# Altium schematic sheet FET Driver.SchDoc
size 431 x 279 mm; Date: Not shown in title block; ApprovedBy: Not shown in title block; CheckedBy: Not shown in title block; Author: Not shown in title block; CompanyName: Not shown in title block; Engineer: Not shown in title block; Organization: Not shown in title block; Address1: Not shown in title block; Address2: Not shown in title block; Address3: Not shown in title block; Address4: Not shown in title block; DocumentNumber: 1; Revision: Use project parameter SCH_Rev; SheetNumber: 2; SheetTotal: 3; PageSetup: Record=PageOptions¦CenterHorizontal=True¦CenterVertical=True¦PrintScale=1.00¦XCorrection=1.00¦YCorrection=1.00¦PrintKind=0¦BorderSize=5000000¦LeftOffset=0¦BottomOffset=0¦Orientation=2¦PaperLength=1000¦PaperWidth=1000¦Scale=100¦PaperSource=15¦PrintQuality=600¦MediaType=1¦DitherType=10¦PaperKind=Letter¦PrintScaleMode=1
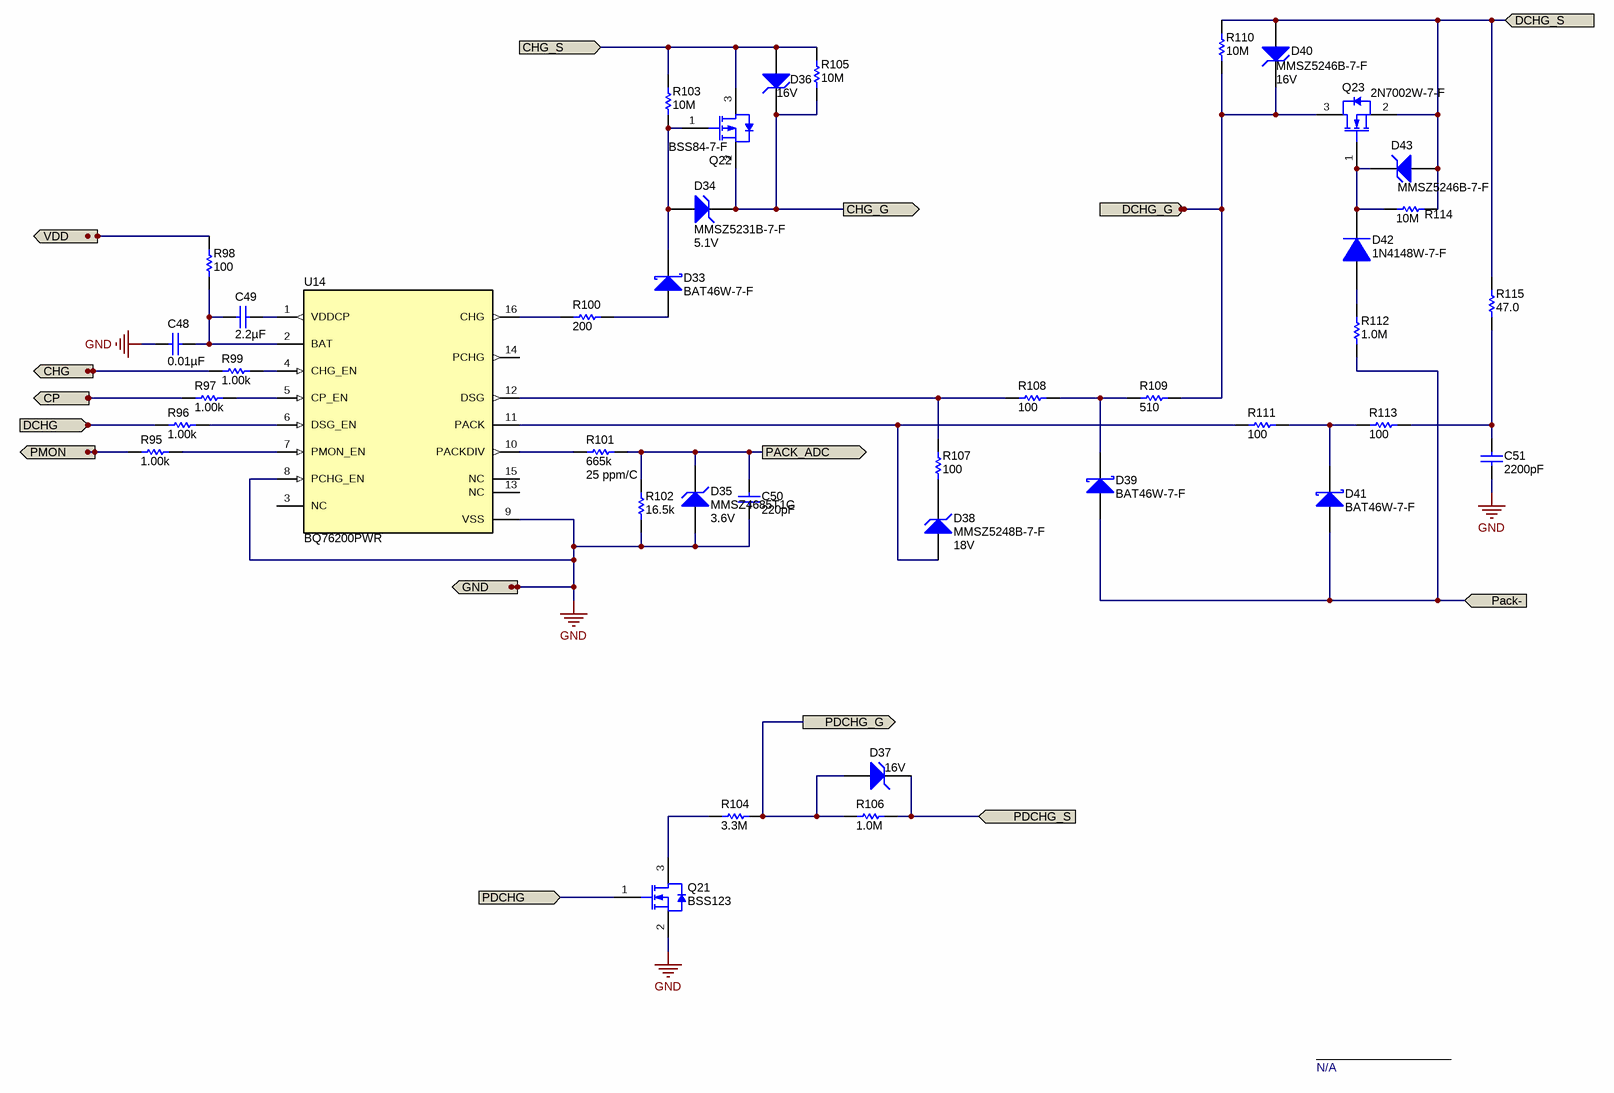
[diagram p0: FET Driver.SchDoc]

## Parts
C48  ValueDisplayed: 0.01µF  [0603]  (hidden comment: GRM188R72A103KA01D)
C49  ValueDisplayed: 2.2µF  [0805_HV]  (hidden comment: C2012X7R1V225K085AC)
C50  ValueDisplayed: 220pF  [0603]  (hidden comment: GRM188R71H221KA01D)
C51  ValueDisplayed: 2200pF  [0603]  (hidden comment: 06031C222JAT2A)
D33  BAT46W-7-F  [SOD-123]
D34  MMSZ5231B-7-F  value 5.1V  [SOD-123]
D35  MMSZ4685T1G  value 3.6V  [SOD-123]
D36  value 16V  [SOD-123]  (hidden comment: MMSZ5246B-7-F)
D37  value 16V  [SOD-123]  (hidden comment: MMSZ5246B-7-F)
D38  MMSZ5248B-7-F  value 18V  [SOD-123]
D39  BAT46W-7-F  [SOD-123]
D40  MMSZ5246B-7-F  value 16V  [SOD-123]
D41  BAT46W-7-F  [SOD-123]
D42  1N4148W-7-F  [SOD-123]
D43  MMSZ5246B-7-F  [SOD-123]
Q21  BSS123  [SOT-23]
Q22  BSS84-7-F  [SOT-23]
Q23  2N7002W-7-F  [SOT-323]
R95  ValueDisplayed: 1.00k  [0603]  (hidden comment: CRCW06031K00FKEA)
R96  ValueDisplayed: 1.00k  [0603]  (hidden comment: CRCW06031K00FKEA)
R97  ValueDisplayed: 1.00k  [0603]  (hidden comment: CRCW06031K00FKEA)
R98  ValueDisplayed: 100  [0603]  (hidden comment: CRCW0603100RFKEA)
R99  ValueDisplayed: 1.00k  [0603]  (hidden comment: CRCW06031K00FKEA)
R100  ValueDisplayed: 200  [0603]  (hidden comment: CRCW0603200RFKEA)
R101  ValueDisplayed: 665k  TempCo: 25 ppm/C  [0603]  (hidden comment: RT0603BRD07665KL)
R102  ValueDisplayed: 16.5k  [0603]  (hidden comment: RT0603BRD0716K5L)
R103  ValueDisplayed: 10M  [0603]  (hidden comment: CRCW060310M0JNEA)
R104  ValueDisplayed: 3.3M  [0603]  (hidden comment: CRCW06033M30JNEA)
R105  ValueDisplayed: 10M  [0603]  (hidden comment: CRCW060310M0JNEA)
R106  ValueDisplayed: 1.0M  [0603]  (hidden comment: CRCW06031M00JNEA)
R107  ValueDisplayed: 100  [0603]  (hidden comment: CRCW0603100RFKEA)
R108  ValueDisplayed: 100  [0603S]  (hidden comment: CRCW0603100RFKEA)
R109  ValueDisplayed: 510  [0603]  (hidden comment: CRCW0603510RJNEA)
R110  ValueDisplayed: 10M  [0603]  (hidden comment: CRCW060310M0JNEA)
R111  ValueDisplayed: 100  [0603]  (hidden comment: CRCW0603100RFKEA)
R112  ValueDisplayed: 1.0M  [0603]  (hidden comment: CRCW06031M00JNEA)
R113  ValueDisplayed: 100  [0603]  (hidden comment: CRCW0603100RFKEA)
R114  ValueDisplayed: 10M  [0603]  (hidden comment: CRCW060310M0JNEA)
R115  ValueDisplayed: 47.0  [0603]  (hidden comment: RC0603FR-0747RL)
U14  BQ76200PWR  [PW0016A_L]

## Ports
CHG (in), CHG_G (out), CHG_S (in), CP (in), DCHG (in), DCHG_G (out), DCHG_S (in), GND (in), Pack- (in), PACK_ADC (out), PDCHG (in), PDCHG_G (out), PDCHG_S (in), PMON (in), VDD (in)

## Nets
GND: C48.2 C50.2 C51.2 D35.2(A) Q21.2(S) R102.1 U14.8(PCHG_EN) U14.9(VSS) ; port GND
CHG: R99.1 ; port CHG
CHG_G: D34.1(K) D36.1(K) Q22.2(S) R105.1 ; port CHG_G
CHG_S: D36.2(A) Q22.3(D) R103.2 R105.2 ; port CHG_S
CP: R97.1 ; port CP
DCHG: R96.1 ; port DCHG
DCHG_G: D40.1(K) Q23.3(D) R109.2 R110.1 ; port DCHG_G
DCHG_S: D40.2(A) D43.2(A) Q23.2(S) R110.2 R114.1 R115.2 ; port DCHG_S
Pack-: D39.2(A) D41.2(A) R112.1 ; port Pack-
PACK_ADC: C50.1 D35.1(K) R101.2 R102.2 ; port PACK_ADC
PDCHG: Q21.1(G) ; port PDCHG
PDCHG_G: D37.2(A) R104.2 R106.1 ; port PDCHG_G
PDCHG_S: D37.1(K) R106.2 ; port PDCHG_S
PMON: R95.1 ; port PMON
VDD: R98.2 ; port VDD
NetC48_1: C48.1 C49.2 R98.1 U14.2(BAT)
NetC49_1: C49.1 U14.1(VDDCP)
NetC51_1: C51.1 R113.2 R115.1
NetD33_1: D33.1(K) D34.2(A) Q22.1(G) R103.1
NetD33_2: D33.2(A) R100.2
NetD38_1: D38.1(K) R107.1
NetD38_2: D38.2(A) R111.1 U14.11(PACK)
NetD39_1: D39.1(K) R108.2 R109.1
NetD41_1: D41.1(K) R111.2 R113.1
NetD42_1: D42.1(K) D43.1(K) Q23.1(G) R114.2
NetD42_2: D42.2(A) R112.2
NetQ21_3: Q21.3(D) R104.1
NetR95_2: R95.2 U14.7(PMON_EN)
NetR96_2: R96.2 U14.6(DSG_EN)
NetR97_2: R97.2 U14.5(CP_EN)
NetR99_2: R99.2 U14.4(CHG_EN)
NetR100_1: R100.1 U14.16(CHG)
NetR101_1: R101.1 U14.10(PACKDIV)
NetR107_2: R107.2 R108.1 U14.12(DSG)

Not connected (* = marked no-connect by the designer): U14 3(NC) 13(NC) 14(PCHG) 15(NC)

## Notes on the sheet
- N/A

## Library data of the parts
C48 = GRM188R72A103KA01D: CAP, CERM, 0.01 µF, 100 V,+/- 10%, X7R, 0603; Manufacturer: MuRata; Polarized: N; CompType: Capacitor; Value: 0.01uF; U/M: EA; Cap_F: 0.00000001; Tolerance_%: 10; VDC_V: 100; Value2: 100V; TaMin_C: -55; TaMax_C: 125; SizeArea_mm2: 1.28; SizeAreaWB_mm2: 4.68; SizeX_mm: 1.6; SizeY_mm: 0.8; SizeZ_mm: 1; AEC Category: Q200; Green_Lifecycle: Active; Green_REACh: Passed
C49 = C2012X7R1V225K085AC: CAP, CERM, 2.2 µF, 35 V,+/- 10%, X7R, 0805; Manufacturer: TDK; Polarized: N; CompType: Capacitor; Value: 2.2uF; U/M: EA; Cap_F: 0.0000022; Tolerance_%: 10; VDC_V: 35; Value2: 35V; TaMin_C: -55; TaMax_C: 125; Cap_Case: 0805; SizeArea_mm2: 2.5; SizeAreaWB_mm2: 6.75; SizeX_mm: 2; SizeY_mm: 1.25; SizeZ_mm: 1.45; AEC Category: Q200
C50 = GRM188R71H221KA01D: CAP, CERM, 220 pF, 50 V,+/- 10%, X7R, 0603; Manufacturer: MuRata; Polarized: N; CompType: Capacitor; Value: 220pF; U/M: EA; Cap_F: 0.00000000022; Tolerance_%: 10; VDC_V: 50; Value2: 50V; TaMin_C: -55; TaMax_C: 125; SizeArea_mm2: 1.28; SizeAreaWB_mm2: 4.68; SizeX_mm: 1.6; SizeY_mm: 0.8; SizeZ_mm: 1; AEC Category: Q200; Green_Lifecycle: Active; Green_REACh: Passed
C51 = 06031C222JAT2A: CAP, CERM, 2200 pF, 100 V,+/- 5%, X7R, 0603; Manufacturer: AVX; Polarized: N; CompType: Capacitor; Value: 2200pF; U/M: EA; Cap_F: 0.0000000022; Tolerance_%: 5; ESR_ohm: 0.192; Value1: 0.192 ohm; VDC_V: 100; Value2: 100V; TaMin_C: -55; TaMax_C: 125; SizeArea_mm2: 1.28; SizeAreaWB_mm2: 4.68; SizeX_mm: 1.6; SizeY_mm: 0.8; SizeZ_mm: 1; AEC Category: Q200; Green_Lifecycle: Active; Green_REACh: Passed
D33 D39 D41 = BAT46W-7-F: Diode, Schottky, 100 V, 0.15 A, SOD-123; Manufacturer: Diodes Inc.; U/M: EA; Vf_V: 0.6; Value: 100V; Value1: 0.15A; Value2: 0.6V; Io_A: 0.15; Vr_V: 100; SizeAreaWB_mm2: 13.095; SizeArea_mm2: 6.545; SizeX_mm: 3.85; SizeY_mm: 1.7; SizeZ_mm: 1.35; AEC Category: Q101; Green_Lifecycle: Active; Green_REACh: Passed
D34 = MMSZ5231B-7-F: Diode, Zener, 5.1 V, 500 mW, SOD-123; Manufacturer: Diodes Inc.; SymbolCreator: a0412235; U/M: EA; Power_W: 0.5; Vz_V: 5.1; Value1: 0.5W; RJA_CperW: 350; SizeAreaWB_mm2: 13.095; SizeArea_mm2: 6.545; SizeX_mm: 3.85; SizeY_mm: 1.7; SizeZ_mm: 1.35; AEC Category: Q101; Green_Lifecycle: Active; Green_REACh: Passed
D35 = MMSZ4685T1G: Diode, Zener, 3.6 V, 500 mW, SOD-123; Manufacturer: ON Semiconductor; SymbolCreator: a0412235; U/M: EA; Power_W: 0.5; Vz_V: 3.6; Value1: 0.5W; RJA_CperW: 340; SizeAreaWB_mm2: 13.095; SizeArea_mm2: 6.545; SizeX_mm: 3.85; SizeY_mm: 1.7; SizeZ_mm: 1.35; AEC Category: Q101; Green_Lifecycle: Active; Green_REACh: Passed
D36 D37 D40 = MMSZ5246B-7-F: Diode, Zener, 16 V, 500 mW, SOD-123; Manufacturer: Diodes Inc.; SymbolCreator: a0412235; U/M: EA; Power_W: 0.5; Vz_V: 16; Value1: 0.5W; RJA_CperW: 350; SizeAreaWB_mm2: 13.095; SizeArea_mm2: 6.545; SizeX_mm: 3.85; SizeY_mm: 1.7; SizeZ_mm: 1.35; AEC Category: Q101; Green_Lifecycle: Active; Green_REACh: Passed
D38 = MMSZ5248B-7-F: Diode, Zener, 18 V, 500 mW, SOD-123; Manufacturer: Diodes Inc.; SymbolCreator: a0412235; U/M: EA; Power_W: 0.5; Vz_V: 18; Value1: 0.5W; RJA_CperW: 350; SizeAreaWB_mm2: 13.095; SizeArea_mm2: 6.545; SizeX_mm: 3.85; SizeY_mm: 1.7; SizeZ_mm: 1.35; AEC Category: Q101; Green_Lifecycle: Active; Green_REACh: Passed
D42 = 1N4148W-7-F: Diode, Ultrafast, 100 V, 0.15 A, SOD-123; Manufacturer: Diodes Inc.; U/M: EA; Vf_V: 1.25; Value: 100V; Value1: 0.15A; Value2: 1.25V; Io_A: 0.15; Vr_V: 100; TJmax_C: 150; SizeAreaWB_mm2: 13.095; SizeArea_mm2: 6.545; SizeX_mm: 3.85; SizeY_mm: 1.7; SizeZ_mm: 1.35; AEC Category: Q101; Green_Lifecycle: Active; Green_REACh: Passed
D43 = MMSZ5246B-7-F: Diode, Zener, 16 V, 500 mW, SOD-123; Manufacturer: Diodes Inc.; SymbolCreator: a0412235; Value: 16V; U/M: EA; Power_W: 0.5; Vz_V: 16; Value1: 0.5W; RJA_CperW: 350; SizeAreaWB_mm2: 13.095; SizeArea_mm2: 6.545; SizeX_mm: 3.85; SizeY_mm: 1.7; SizeZ_mm: 1.35; AEC Category: Q101; Green_Lifecycle: Active; Green_REACh: Passed
Q21 = BSS123: MOSFET, N-CH, 100 V, 0.17 A, SOT-23; Manufacturer: Fairchild Semiconductor; Alternate Manufacturer: None; U/M: EA; ChType: N; Value: 100V; VdsMax_V: 100; Value1: 10 ohm; Rdson45_ohm: 10; Value2: 1.8 nC; QgTyp_nC: 1.8; Vgs_V: 20; IdsMax_A: 0.17; SizeAreaWB_mm2: 14; SizeArea_mm2: 7.5; SizeX_mm: 2.5; SizeY_mm: 3; SizeZ_mm: 1.1; AEC Category: Q101; Green_Lifecycle: Active; Green_REACh: Passed
Q22 = BSS84-7-F: MOSFET, P-CH, -50 V, -0.13 A, SOT-23; Manufacturer: Diodes Inc.; Alternate Manufacturer: None; U/M: EA; ChType: P; Value: -50V; Value1: ? ohm; Value2: ? nC; Vgs_V: -20; SizeAreaWB_mm2: 14; SizeArea_mm2: 7.5; SizeX_mm: 2.5; SizeY_mm: 3; SizeZ_mm: 1.1; AEC Category: Q101; AEC Qualified: N; Green_Lifecycle: Active; Green_REACh: Passed
Q23 = 2N7002W-7-F: MOSFET, N-CH, 60 V, 0.115 A, SOT-323; Manufacturer: Diodes Inc.; Alternate Manufacturer: None; U/M: EA; ChType: N; Value: 60V; VdsMax_V: 60; Value1: 7.5 ohm; Rdson45_ohm: 7.5; Value2: ? nC; Vgs_V: 20; IdsMax_A: 0.115; SizeAreaWB_mm2: 10.24; SizeArea_mm2: 4.84; SizeX_mm: 2.2; SizeZ_mm: 1.1; AEC Category: Q101; Green_Lifecycle: Active; Green_REACh: Passed
R95-R97 R99 = CRCW06031K00FKEA: RES, 1.00 k, 1%, 0.1 W, 0603; Manufacturer: Vishay-Dale; CompType: Resistor; Value: 1.00k; Res_ohm: 1000; Value_Code: 1k00; Tolerance_%: 1; Power_W: 0.1; Value2: 0.1W; VDC_V: 75; TempCo: 100 ppm/C; SizeArea_mm2: 1.28; SizeX_mm: 1.6; SizeY_mm: 0.8; EIA_Code: E96; U/M: EA; AEC Category: Q200; Green_Lifecycle: Active; Green_REACh: Passed
R98 R107 R108 R111 R113 = CRCW0603100RFKEA: RES, 100, 1%, 0.1 W, 0603; Manufacturer: Vishay-Dale; CompType: Resistor; Value: 100; Value_Code: 100R; Tolerance_%: 1; Power_W: 0.1; Value2: 0.1W; VDC_V: 75; TempCo: 100 ppm/C; SizeArea_mm2: 1.28; SizeX_mm: 1.6; SizeY_mm: 0.8; EIA_Code: E96; U/M: EA; AEC Category: Q200; Green_Lifecycle: Active; Green_REACh: Passed
R100 = CRCW0603200RFKEA: RES, 200, 1%, 0.1 W, 0603; Manufacturer: Vishay-Dale; CompType: Resistor; Value: 200; Value_Code: 200R; Tolerance_%: 1; Power_W: 0.1; Value2: 0.1W; VDC_V: 75; TempCo: 100 ppm/C; SizeArea_mm2: 1.28; SizeX_mm: 1.6; SizeY_mm: 0.8; EIA_Code: E96; U/M: EA; AEC Category: Q200; Green_Lifecycle: Active; Green_REACh: Passed
R101 = RT0603BRD07665KL: RES, 665 k, 0.1%, 0.1 W, 0603; Manufacturer: Yageo America; CompType: Resistor; Value: 665k; Res_ohm: 665000; Tolerance_%: 0.1; Value2: 0.1W; VDC_V: 75; SizeArea_mm2: 1.28; SizeX_mm: 1.6; SizeY_mm: 0.8; SizeZ_mm: 1; EIA_Code: E192; U/M: EA; AEC Category: Q200
R102 = RT0603BRD0716K5L: RES, 16.5 k, 0.1%, 0.1 W, 0603; Manufacturer: Yageo America; CompType: Resistor; Value: 16.5k; Res_ohm: 16500; Value_Code: 16k5; Tolerance_%: 0.1; Value2: 0.1W; VDC_V: 75; TempCo: 25 ppm/C; SizeArea_mm2: 1.28; SizeX_mm: 1.6; SizeY_mm: 0.8; SizeZ_mm: 1; EIA_Code: E192; U/M: EA; AEC Category: Q200
R103 R105 R110 R114 = CRCW060310M0JNEA: RES, 10 M, 5%, 0.1 W, 0603; Manufacturer: Vishay-Dale; CompType: Resistor; Value: 10Meg; Res_ohm: 10000000; Value_Code: 10M0; Tolerance_%: 5; Power_W: 0.1; Value2: 0.1W; VDC_V: 75; TempCo: 200 ppm/C; SizeArea_mm2: 1.28; SizeX_mm: 1.6; SizeY_mm: 0.8; SizeZ_mm: 1; EIA_Code: E24; U/M: EA; AEC Category: Q200; Green_Lifecycle: Active; Green_REACh: Passed
R104 = CRCW06033M30JNEA: RES, 3.3 M, 5%, 0.1 W, 0603; Manufacturer: Vishay-Dale; CompType: Resistor; Value: 3.3Meg; Res_ohm: 3300000; Value_Code: 3M30; Tolerance_%: 5; Power_W: 0.1; Value2: 0.1W; VDC_V: 75; TempCo: 200 ppm/C; SizeArea_mm2: 1.28; SizeX_mm: 1.6; SizeY_mm: 0.8; SizeZ_mm: 1; EIA_Code: E24; U/M: EA; AEC Category: Q200; Green_Lifecycle: Active; Green_REACh: Passed
R106 R112 = CRCW06031M00JNEA: RES, 1.0 M, 5%, 0.1 W, 0603; Manufacturer: Vishay-Dale; CompType: Resistor; Value: 1.0Meg; Res_ohm: 1000000; Value_Code: 1M00; Tolerance_%: 5; Power_W: 0.1; Value2: 0.1W; VDC_V: 75; TempCo: 200 ppm/C; SizeArea_mm2: 1.28; SizeX_mm: 1.6; SizeY_mm: 0.8; SizeZ_mm: 1; EIA_Code: E24; U/M: EA; AEC Category: Q200; Green_Lifecycle: Active; Green_REACh: Passed
R109 = CRCW0603510RJNEA: RES, 510, 5%, 0.1 W, 0603; Manufacturer: Vishay-Dale; CompType: Resistor; Value: 510; Value_Code: 510R; Tolerance_%: 5; Power_W: 0.1; Value2: 0.1W; VDC_V: 75; TempCo: 200 ppm/C; SizeArea_mm2: 1.28; SizeX_mm: 1.6; SizeY_mm: 0.8; SizeZ_mm: 1; EIA_Code: E24; U/M: EA; AEC Category: Q200; Green_Lifecycle: Active; Green_REACh: Passed
R115 = RC0603FR-0747RL: RES, 47.0, 1%, 0.1 W, 0603; Manufacturer: Yageo America; CompType: Resistor; Value: 47.0; Res_ohm: 47; Value_Code: 47R0; Tolerance_%: 1; Power_W: 0.1; Value2: 0.1W; VDC_V: 150; TempCo: 200 ppm/C; SizeArea_mm2: 1.28; SizeX_mm: 1.6; SizeY_mm: 0.8; U/M: EA; AEC Category: Q200; Green_Lifecycle: Active; Green_REACh: Passed
U14 = CMP-0076175-1: High-Side N-Channel FET Driver, PW0016A (TSSOP-16); Manufacturer: Texas Instruments; SizeAreaWB_mm2: 58.8; SizeArea_mm2: 32.0; SizeZ_mm: 1.2; SizeY_mm: 5.0; U/M: EA; CompType: IC; SizeX_mm: 6.4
